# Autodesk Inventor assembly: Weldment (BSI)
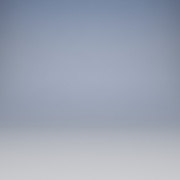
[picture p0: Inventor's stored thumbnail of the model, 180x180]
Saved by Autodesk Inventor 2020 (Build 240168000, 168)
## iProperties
Length Units: 11269
Angle Units: 11283
Time Units: 11279
Mass Units: 11290
Length Display Precision: 3
Angle Display Precision: 2
Part Number: Weldment (BSI)
Document SubType Name: Weldment
Created: 2002-06
Designer: smithga
Created: 2002-08
Designer: F.Stasiak
Weld Material: Welded Aluminum-6061
Manager: www.cadconsulting.pl
Company: Fabian Stasiak CAD Consulting
Control State: 0
Master: False
Shininess: 64.0
Angle Units: 11279
Time Units: 11290
Mass Units: 11283
Compacted: True
Density: 0.0
Volumn: 0.0
Area: 0.0
PropertySet Name: Model Information
Author: F.Stasiak
Subject: Zbiór ćwiczeń. Autodesk Inventor 2020. Kurs podstawowy
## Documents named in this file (1)
- M:\AUTOBUILD\M24_168_RTM\Application\App\Templates\en-US\Metric\Weldment (BSI).iam
